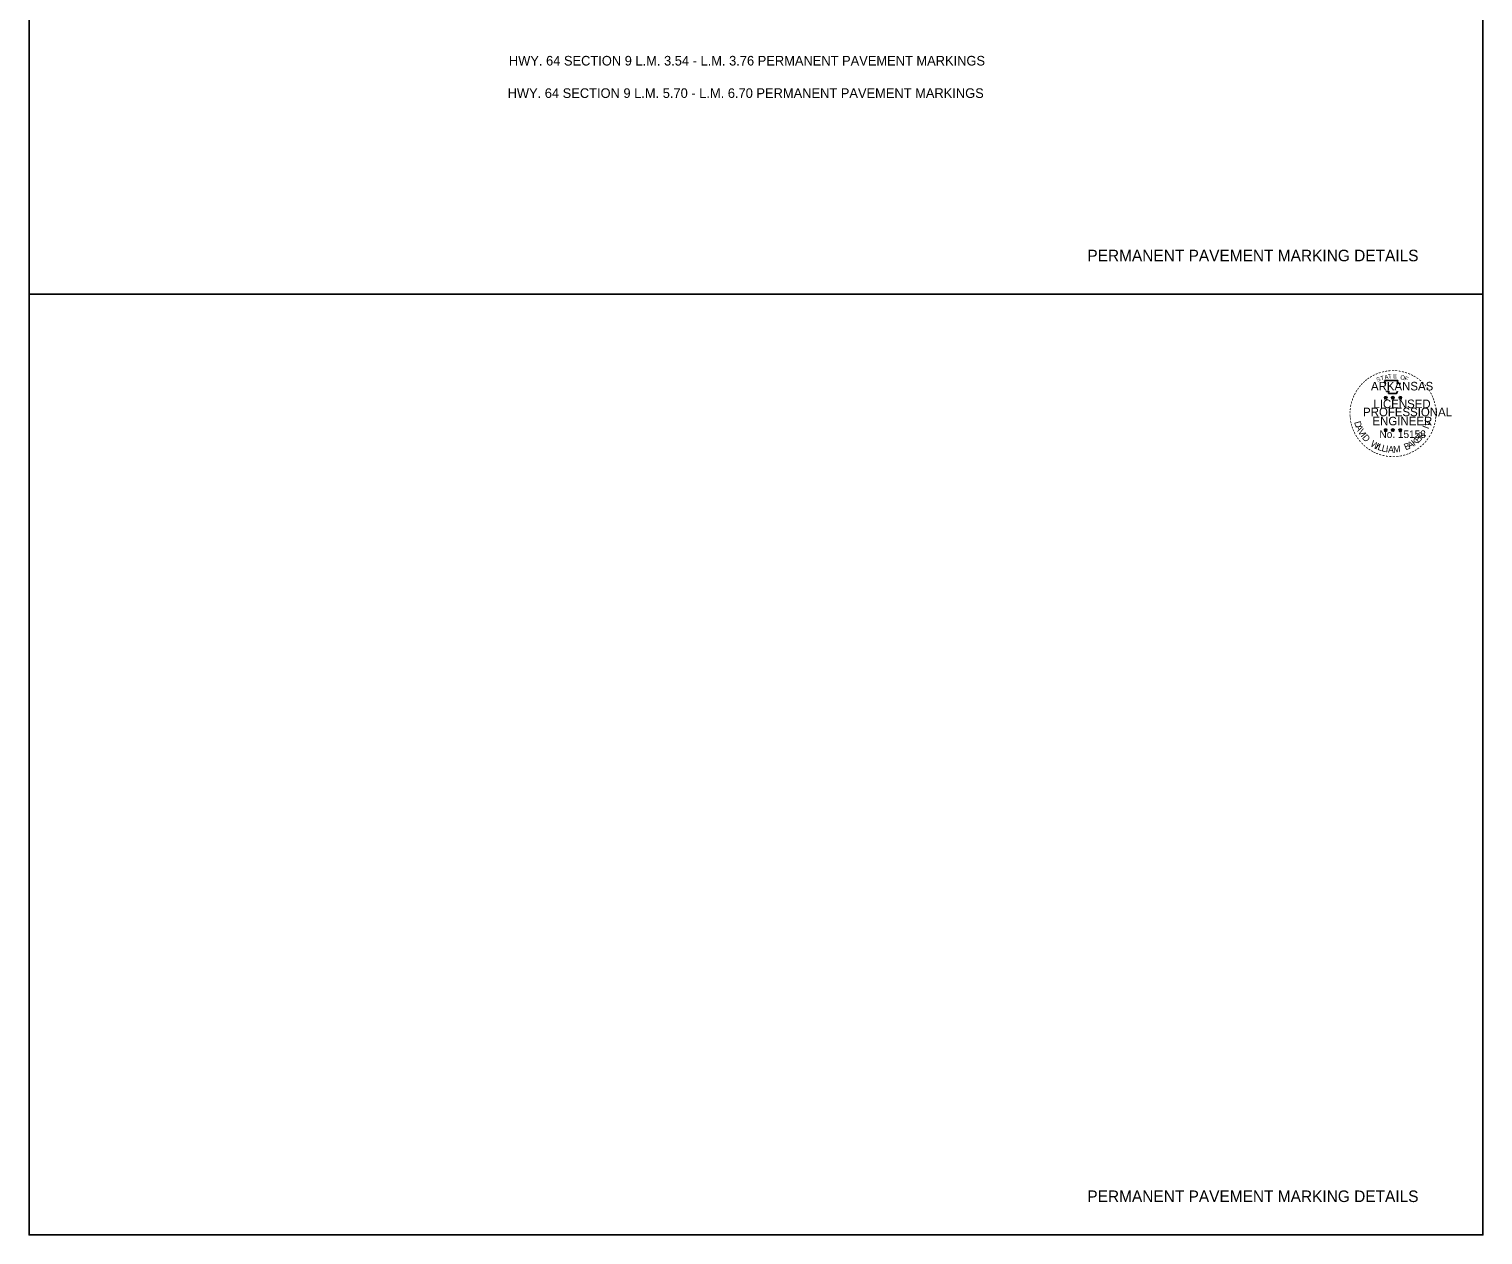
# Model space of a CAD drawing. Extents: x 1373096 to 1373266, y 381130 to 381790.
# Drawn here: x 1373096 to 1373266, y 381130.2 to 381271.2 of the extents above; entities that cross this region are included whole.
import ezdxf

# ---------------------------------------------------------------- set-up
doc = ezdxf.new("R2010")
doc.units = 0
for name, color, linetype in [('Default', 7, 'Continuous'), ('DSN_DRFT_Junk-No-Plot', 7, 'Continuous'), ('R_Border Notes', 7, 'Continuous'), ('R_Border PE', 7, 'Continuous'), ('R_Draft', 7, 'Continuous')]:
    doc.layers.add(name, color=color, linetype=linetype)

msp = doc.modelspace()

# ---------------------------------------------------------------- linework, layer by layer
at = {"layer": 'Default'}
for points in [[(1373095.97, 381350.17), (1373095.97, 381240.17), (1373265.97, 381240.17), (1373265.97, 381350.17)], [(1373095.97, 381240.17), (1373095.97, 381130.17), (1373265.97, 381130.17), (1373265.97, 381240.17)]]:
    msp.add_lwpolyline(points, close=True, dxfattribs=at)
at = {"layer": 'DSN_DRFT_Junk-No-Plot'}
for points in [[(1373095.97, 381350.17), (1373265.97, 381350.17), (1373265.97, 381240.17), (1373095.97, 381240.17)], [(1373095.97, 381350.17), (1373095.97, 381240.17), (1373265.97, 381240.17), (1373265.97, 381350.17)], [(1373095.97, 381240.17), (1373265.97, 381240.17), (1373265.97, 381130.17), (1373095.97, 381130.17)], [(1373095.97, 381240.17), (1373095.97, 381130.17), (1373265.97, 381130.17), (1373265.97, 381240.17)]]:
    msp.add_lwpolyline(points, close=True, dxfattribs=at)
at = {"layer": 'R_Border PE'}
for p, q in [((1373254.43, 381228.13), (1373254.6, 381228.07)), ((1373254.43, 381228.13), (1373254.56, 381228.11)), ((1373254.43, 381228.13), (1373254.55, 381228.07)), ((1373254.5, 381227.93), (1373254.6, 381228.07)), ((1373254.5, 381227.93), (1373254.56, 381228.05)), ((1373254.5, 381227.93), (1373254.6, 381228.03)), ((1373254.6, 381228.26), (1373254.58, 381228.13)), ((1373254.6, 381228.07), (1373254.6, 381228.26)), ((1373254.6, 381228.26), (1373254.63, 381228.13)), ((1373254.78, 381228.13), (1373254.6, 381228.07)), ((1373254.71, 381227.93), (1373254.6, 381228.07)), ((1373254.71, 381227.93), (1373254.6, 381228.03)), ((1373254.78, 381228.13), (1373254.63, 381228.11)), ((1373254.71, 381227.93), (1373254.64, 381228.07)), ((1373254.78, 381228.13), (1373254.67, 381228.08)), ((1373255.26, 381228.13), (1373255.44, 381228.07)), ((1373255.26, 381228.13), (1373255.39, 381228.11)), ((1373255.26, 381228.13), (1373255.38, 381228.07)), ((1373255.33, 381227.93), (1373255.44, 381228.07)), ((1373255.33, 381227.93), (1373255.39, 381228.05)), ((1373255.33, 381227.93), (1373255.44, 381228.03)), ((1373255.44, 381228.26), (1373255.42, 381228.13)), ((1373255.44, 381228.07), (1373255.44, 381228.26)), ((1373255.44, 381228.26), (1373255.46, 381228.13)), ((1373255.61, 381228.13), (1373255.44, 381228.07)), ((1373255.54, 381227.93), (1373255.44, 381228.07)), ((1373255.54, 381227.93), (1373255.44, 381228.03)), ((1373255.61, 381228.13), (1373255.47, 381228.11)), ((1373255.54, 381227.93), (1373255.48, 381228.07)), ((1373255.61, 381228.13), (1373255.51, 381228.08)), ((1373256.15, 381228.12), (1373256.32, 381228.07)), ((1373256.15, 381228.12), (1373256.27, 381228.1)), ((1373256.15, 381228.12), (1373256.26, 381228.06)), ((1373256.21, 381227.92), (1373256.32, 381228.07)), ((1373256.21, 381227.92), (1373256.28, 381228.04)), ((1373256.21, 381227.92), (1373256.32, 381228.03)), ((1373256.32, 381228.25), (1373256.3, 381228.12)), ((1373256.32, 381228.07), (1373256.32, 381228.25)), ((1373256.32, 381228.25), (1373256.34, 381228.13)), ((1373256.49, 381228.12), (1373256.32, 381228.07)), ((1373256.43, 381227.92), (1373256.32, 381228.07)), ((1373256.43, 381227.92), (1373256.32, 381228.03)), ((1373256.49, 381228.12), (1373256.35, 381228.1)), ((1373256.43, 381227.92), (1373256.36, 381228.07)), ((1373256.49, 381228.12), (1373256.39, 381228.07)), ((1373254.43, 381224.34), (1373254.6, 381224.29)), ((1373254.43, 381224.34), (1373254.55, 381224.32)), ((1373254.43, 381224.34), (1373254.55, 381224.28)), ((1373254.49, 381224.14), (1373254.6, 381224.29)), ((1373254.49, 381224.14), (1373254.56, 381224.26)), ((1373254.49, 381224.14), (1373254.6, 381224.25)), ((1373254.6, 381224.47), (1373254.58, 381224.34)), ((1373254.6, 381224.29), (1373254.6, 381224.47)), ((1373254.6, 381224.47), (1373254.63, 381224.35)), ((1373254.77, 381224.34), (1373254.6, 381224.29)), ((1373254.71, 381224.14), (1373254.6, 381224.29)), ((1373254.71, 381224.14), (1373254.6, 381224.25)), ((1373254.77, 381224.34), (1373254.63, 381224.32)), ((1373254.71, 381224.14), (1373254.64, 381224.28)), ((1373254.77, 381224.34), (1373254.67, 381224.29)), ((1373255.26, 381224.34), (1373255.44, 381224.29)), ((1373255.26, 381224.34), (1373255.39, 381224.32)), ((1373255.26, 381224.34), (1373255.38, 381224.28)), ((1373255.33, 381224.14), (1373255.44, 381224.29)), ((1373255.33, 381224.14), (1373255.39, 381224.26)), ((1373255.33, 381224.14), (1373255.43, 381224.25)), ((1373255.44, 381224.47), (1373255.42, 381224.34)), ((1373255.54, 381224.14), (1373255.43, 381224.25)), ((1373255.44, 381224.29), (1373255.44, 381224.47)), ((1373255.44, 381224.47), (1373255.46, 381224.35)), ((1373255.61, 381224.34), (1373255.44, 381224.29)), ((1373255.54, 381224.14), (1373255.44, 381224.29)), ((1373255.61, 381224.34), (1373255.47, 381224.32)), ((1373255.54, 381224.14), (1373255.47, 381224.28)), ((1373255.61, 381224.34), (1373255.51, 381224.29)), ((1373256.14, 381224.34), (1373256.32, 381224.28)), ((1373256.14, 381224.34), (1373256.27, 381224.32)), ((1373256.14, 381224.34), (1373256.26, 381224.28)), ((1373256.21, 381224.13), (1373256.32, 381224.28)), ((1373256.21, 381224.13), (1373256.27, 381224.26)), ((1373256.21, 381224.13), (1373256.32, 381224.24)), ((1373256.32, 381224.47), (1373256.3, 381224.34)), ((1373256.32, 381224.28), (1373256.32, 381224.47)), ((1373256.32, 381224.47), (1373256.34, 381224.34)), ((1373256.49, 381224.34), (1373256.32, 381224.28)), ((1373256.43, 381224.13), (1373256.32, 381224.28)), ((1373256.43, 381224.13), (1373256.32, 381224.24)), ((1373256.49, 381224.34), (1373256.35, 381224.31)), ((1373256.43, 381224.13), (1373256.36, 381224.28)), ((1373256.49, 381224.34), (1373256.39, 381224.29))]:
    msp.add_line(p, q, dxfattribs=at)
for points in [[(1373254.45, 381230.07), (1373254.58, 381229.66)], [(1373256.2, 381229.61), (1373256.28, 381229.75), (1373255.93, 381229.74), (1373256.01, 381230.07), (1373254.45, 381230.07)], [(1373254.7, 381228.86), (1373254.7, 381228.81), (1373254.98, 381228.8), (1373254.95, 381228.57), (1373255.88, 381228.57), (1373255.99, 381228.84)], [(1373254.6, 381228.26), (1373254.71, 381227.93), (1373254.43, 381228.13), (1373254.78, 381228.13), (1373254.5, 381227.93), (1373254.6, 381228.26)], [(1373255.44, 381228.26), (1373255.54, 381227.93), (1373255.26, 381228.13), (1373255.61, 381228.13), (1373255.33, 381227.93), (1373255.44, 381228.26)], [(1373256.32, 381228.25), (1373256.43, 381227.92), (1373256.15, 381228.12), (1373256.49, 381228.12), (1373256.21, 381227.92), (1373256.32, 381228.25)], [(1373254.6, 381224.47), (1373254.71, 381224.14), (1373254.43, 381224.34), (1373254.77, 381224.34), (1373254.49, 381224.14), (1373254.6, 381224.47)], [(1373255.44, 381224.47), (1373255.54, 381224.14), (1373255.26, 381224.34), (1373255.61, 381224.34), (1373255.33, 381224.14), (1373255.44, 381224.47)], [(1373256.32, 381224.47), (1373256.43, 381224.13), (1373256.14, 381224.34), (1373256.49, 381224.34), (1373256.21, 381224.13), (1373256.32, 381224.47)]]:
    msp.add_lwpolyline(points, dxfattribs=at)
for centre, radius in [((1373254.6, 381228.07), 0.0861), ((1373254.6, 381228.07), 0.0723), ((1373254.6, 381228.07), 0.0579), ((1373254.6, 381228.07), 0.0495), ((1373254.6, 381228.07), 0.0374), ((1373254.6, 381228.07), 0.0248), ((1373254.6, 381228.07), 0.0148), ((1373255.44, 381228.07), 0.0861), ((1373255.44, 381228.07), 0.0723), ((1373255.44, 381228.07), 0.0579), ((1373255.44, 381228.07), 0.0495), ((1373255.44, 381228.07), 0.0374), ((1373255.44, 381228.07), 0.0248), ((1373255.44, 381228.07), 0.0148), ((1373256.32, 381228.07), 0.0861), ((1373256.32, 381228.07), 0.0723), ((1373256.32, 381228.07), 0.0579), ((1373256.32, 381228.07), 0.0495), ((1373256.32, 381228.07), 0.0374), ((1373256.32, 381228.07), 0.0248), ((1373256.32, 381228.07), 0.0148), ((1373254.6, 381224.29), 0.0861), ((1373254.6, 381224.29), 0.0723), ((1373254.6, 381224.29), 0.0579), ((1373254.6, 381224.29), 0.0495), ((1373254.6, 381224.29), 0.0374), ((1373254.6, 381224.29), 0.0248), ((1373254.6, 381224.29), 0.0148), ((1373255.44, 381224.29), 0.0861), ((1373255.44, 381224.29), 0.0723), ((1373255.44, 381224.29), 0.0579), ((1373255.44, 381224.29), 0.0495), ((1373255.44, 381224.29), 0.0374), ((1373255.44, 381224.29), 0.0248), ((1373255.44, 381224.29), 0.0148), ((1373256.32, 381224.28), 0.0861), ((1373256.32, 381224.28), 0.0723), ((1373256.32, 381224.28), 0.0579), ((1373256.32, 381224.28), 0.0495), ((1373256.32, 381224.28), 0.0374), ((1373256.32, 381224.28), 0.0248), ((1373256.32, 381224.28), 0.0148)]:
    msp.add_circle(centre, radius, dxfattribs=at)

# ---------------------------------------------------------------- texts
at = {"layer": 'R_Border Notes'}
for p in [(1373219.72, 381244.02), (1373219.72, 381134.02)]:
    msp.add_text('PERMANENT PAVEMENT MARKING DETAILS', height=1.35, dxfattribs=at).set_placement(p)
at = {"layer": 'R_Border PE'}
for s, height, rotation, p in [('-', 0.8, 38.9507, (1373252.36, 381229.77)), ('-', 0.8, 36.2317, (1373252.6, 381229.96)), ('-', 0.8, 34.0636, (1373252.89, 381230.15)), ('-', 0.8, 28.7918, (1373253.19, 381230.34)), ('-', 0.8, 24.3072, (1373253.51, 381230.5)), ('S', 0.5, 21.594, (1373253.63, 381229.91)), ('-', 0.8, 19.1761, (1373253.82, 381230.63)), ('T', 0.5, 16.4036, (1373254.08, 381230.07)), ('-', 0.8, 13.6302, (1373254.2, 381230.75)), ('A', 0.5, 11.2132, (1373254.5, 381230.2)), ('-', 0.8, 10.2193, (1373254.54, 381230.83)), ('T', 0.5, 6.0228, (1373254.92, 381230.28)), ('-', 0.8, 5.8968, (1373254.9, 381230.89)), ('-', 0.8, 0.1862, (1373255.29, 381230.92)), ('E', 0.5, 0.8323, (1373255.47, 381230.34)), ('-', 0.8, 357.743, (1373255.65, 381230.92)), ('-', 0.8, 352.1617, (1373256.02, 381230.89)), ('O', 0.5, 350.4515, (1373256.28, 381230.23)), ('-', 0.8, 347.2049, (1373256.38, 381230.83)), ('F', 0.5, 340.0707, (1373256.75, 381230.12)), ('-', 0.8, 342.3362, (1373256.7, 381230.76)), ('-', 0.8, 337.8551, (1373257.07, 381230.64)), ('-', 0.8, 334.1211, (1373257.38, 381230.51)), ('-', 0.8, 329.6409, (1373257.67, 381230.37)), ('-', 0.8, 325.8627, (1373257.99, 381230.19)), ('-', 0.8, 320.5297, (1373258.3, 381229.97)), ('-', 0.8, 62.8713, (1373251.2, 381228.22)), ('-', 0.8, 58.0706, (1373251.35, 381228.53)), ('-', 0.8, 54.2325, (1373251.52, 381228.79)), ('-', 0.8, 50.6142, (1373251.72, 381229.08)), ('-', 0.8, 48.4231, (1373251.92, 381229.32)), ('-', 0.8, 42.9622, (1373252.15, 381229.56)), ('-', 0.8, 315.5786, (1373258.6, 381229.73)), ('-', 0.8, 309.8797, (1373258.88, 381229.45)), ('-', 0.8, 306.6522, (1373259.14, 381229.15)), ('-', 0.7, 303.6753, (1373259.39, 381228.87)), ('-', 0.8, 299.6684, (1373259.55, 381228.57)), ('-', 0.8, 85.1863, (1373250.75, 381226.54)), ('-', 0.8, 81.2013, (1373250.79, 381226.89)), ('-', 0.8, 75.461, (1373250.86, 381227.25)), ('-', 0.8, 72.3945, (1373250.96, 381227.6)), ('-', 0.8, 67.7743, (1373251.07, 381227.92)), ('-', 0.8, 294.6628, (1373259.71, 381228.26)), ('-', 0.8, 290.5728, (1373259.84, 381227.97)), ('-', 0.8, 285.1233, (1373259.95, 381227.68)), ('-', 0.8, 280.5493, (1373260.05, 381227.31)), ('-', 0.8, 276.5962, (1373260.13, 381226.93)), ('-', 0.8, 94.1959, (1373250.76, 381225.83)), ('-', 0.8, 89.0622, (1373250.74, 381226.19)), ('-', 0.8, 98.9479, (1373250.8, 381225.5)), ('-', 0.8, 101.7149, (1373250.86, 381225.13)), ('-', 0.8, 105.4578, (1373250.94, 381224.83)), ('D', 0.77, 286.2848, (1373250.91, 381225.2)), ('V', 0.77, 72.6573, (1373259.7, 381224.62)), ('-', 0.8, 255.7626, (1373260.08, 381225.25)), ('-', 0.8, 260.9953, (1373260.14, 381225.59)), ('-', 0.8, 263.5172, (1373260.17, 381225.92)), ('-', 0.8, 274.3301, (1373260.16, 381226.57)), ('-', 0.8, 269.9407, (1373260.18, 381226.25)), ('-', 0.8, 109.0874, (1373251.05, 381224.52)), ('-', 0.8, 114.0643, (1373251.18, 381224.22)), ('-', 0.8, 115.7289, (1373251.33, 381223.91)), ('-', 0.8, 120.4471, (1373251.51, 381223.62)), ('A', 0.77, 292.7835, (1373251.05, 381224.7)), ('-', 0.8, 125.8934, (1373251.71, 381223.34)), ('V', 0.77, 300.7936, (1373251.31, 381224.11)), ('I', 0.77, 308.3502, (1373251.63, 381223.59)), ('D', 0.77, 311.9774, (1373251.8, 381223.36)), ('K', 0.77, 36.9143, (1373257.95, 381222.41)), ('E', 0.77, 44.0175, (1373258.4, 381222.75)), ('R', 0.77, 50.3651, (1373258.77, 381223.11)), ('I', 0.77, 69.0301, (1373259.59, 381224.35)), (',', 0.77, 57.4684, (1373259.13, 381223.55)), ('-', 0.8, 233.8452, (1373259.35, 381223.54)), ('-', 0.8, 239.0712, (1373259.55, 381223.86)), ('-', 0.8, 244.6197, (1373259.75, 381224.24)), ('-', 0.8, 247.8887, (1373259.88, 381224.55)), ('-', 0.8, 252.8681, (1373259.99, 381224.89)), ('-', 0.8, 130.7181, (1373251.94, 381223.06)), ('-', 0.8, 134.2238, (1373252.2, 381222.79)), ('-', 0.8, 138.9338, (1373252.46, 381222.56)), ('-', 0.8, 144.6463, (1373252.74, 381222.35)), ('-', 0.8, 148.0898, (1373253.02, 381222.17)), ('-', 0.8, 151.5704, (1373253.31, 381222.01)), ('W', 0.77, 328.0731, (1373252.74, 381222.47)), ('-', 0.8, 154.6002, (1373253.57, 381221.88)), ('I', 0.77, 336.6877, (1373253.33, 381222.12)), ('-', 0.8, 158.5612, (1373253.88, 381221.76)), ('L', 0.77, 340.3149, (1373253.6, 381222)), ('L', 0.77, 346.6625, (1373254.08, 381221.83)), ('I', 0.77, 353.0101, (1373254.58, 381221.71)), ('A', 0.77, 356.6373, (1373254.86, 381221.66)), ('M', 0.77, 4.6473, (1373255.51, 381221.64)), ('B', 0.77, 22.8589, (1373256.94, 381221.9)), ('A', 0.77, 28.9042, (1373257.39, 381222.09)), ('-', 0.8, 204.2516, (1373257.5, 381221.96)), ('-', 0.8, 207.3568, (1373257.81, 381222.12)), ('-', 0.8, 212.2491, (1373258.09, 381222.29)), ('-', 0.8, 215.7363, (1373258.36, 381222.48)), ('-', 0.8, 221.0851, (1373258.63, 381222.72)), ('-', 0.8, 225.7653, (1373258.9, 381222.97)), ('-', 0.8, 231.2538, (1373259.14, 381223.25)), ('-', 0.8, 162.7983, (1373254.23, 381221.65)), ('-', 0.8, 167.5555, (1373254.59, 381221.57)), ('-', 0.8, 173.1155, (1373254.97, 381221.51)), ('-', 0.8, 176.5183, (1373255.35, 381221.49)), ('-', 0.8, 181.5918, (1373255.72, 381221.49)), ('-', 0.8, 185.8167, (1373256.12, 381221.53)), ('-', 0.8, 191.2858, (1373256.49, 381221.6)), ('-', 0.8, 195.4743, (1373256.85, 381221.7)), ('-', 0.8, 199.4643, (1373257.19, 381221.82))]:
    msp.add_text(s, height=height, rotation=rotation, dxfattribs=at).set_placement(p)
for s, height, p in [('ARKANSAS', 1, (1373252.88, 381228.92)), ('PROFESSIONAL', 1, (1373251.96, 381225.9)), ('LICENSED', 1, (1373253.17, 381226.85)), ('ENGINEER', 1, (1373253.06, 381224.84)), ('No. 15158', 0.878, (1373253.88, 381223.36)), ('AAMU', 0.00001, (1373255.4, 381221.63))]:
    msp.add_text(s, height=height, dxfattribs=at).set_placement(p)
at = {"layer": 'R_Draft'}
for s, p in [('HWY. 64 SECTION 9 L.M. 3.54 - L.M. 3.76 PERMANENT PAVEMENT MARKINGS', (1373152.08, 381266.91)), ('HWY. 64 SECTION 9 L.M. 5.70 - L.M. 6.70 PERMANENT PAVEMENT MARKINGS', (1373151.93, 381263.12))]:
    msp.add_text(s, height=1.125, dxfattribs=at).set_placement(p)

doc.saveas('drawing.dxf')
